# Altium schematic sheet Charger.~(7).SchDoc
size A3; SheetNumber: 2; SheetTotal: 2
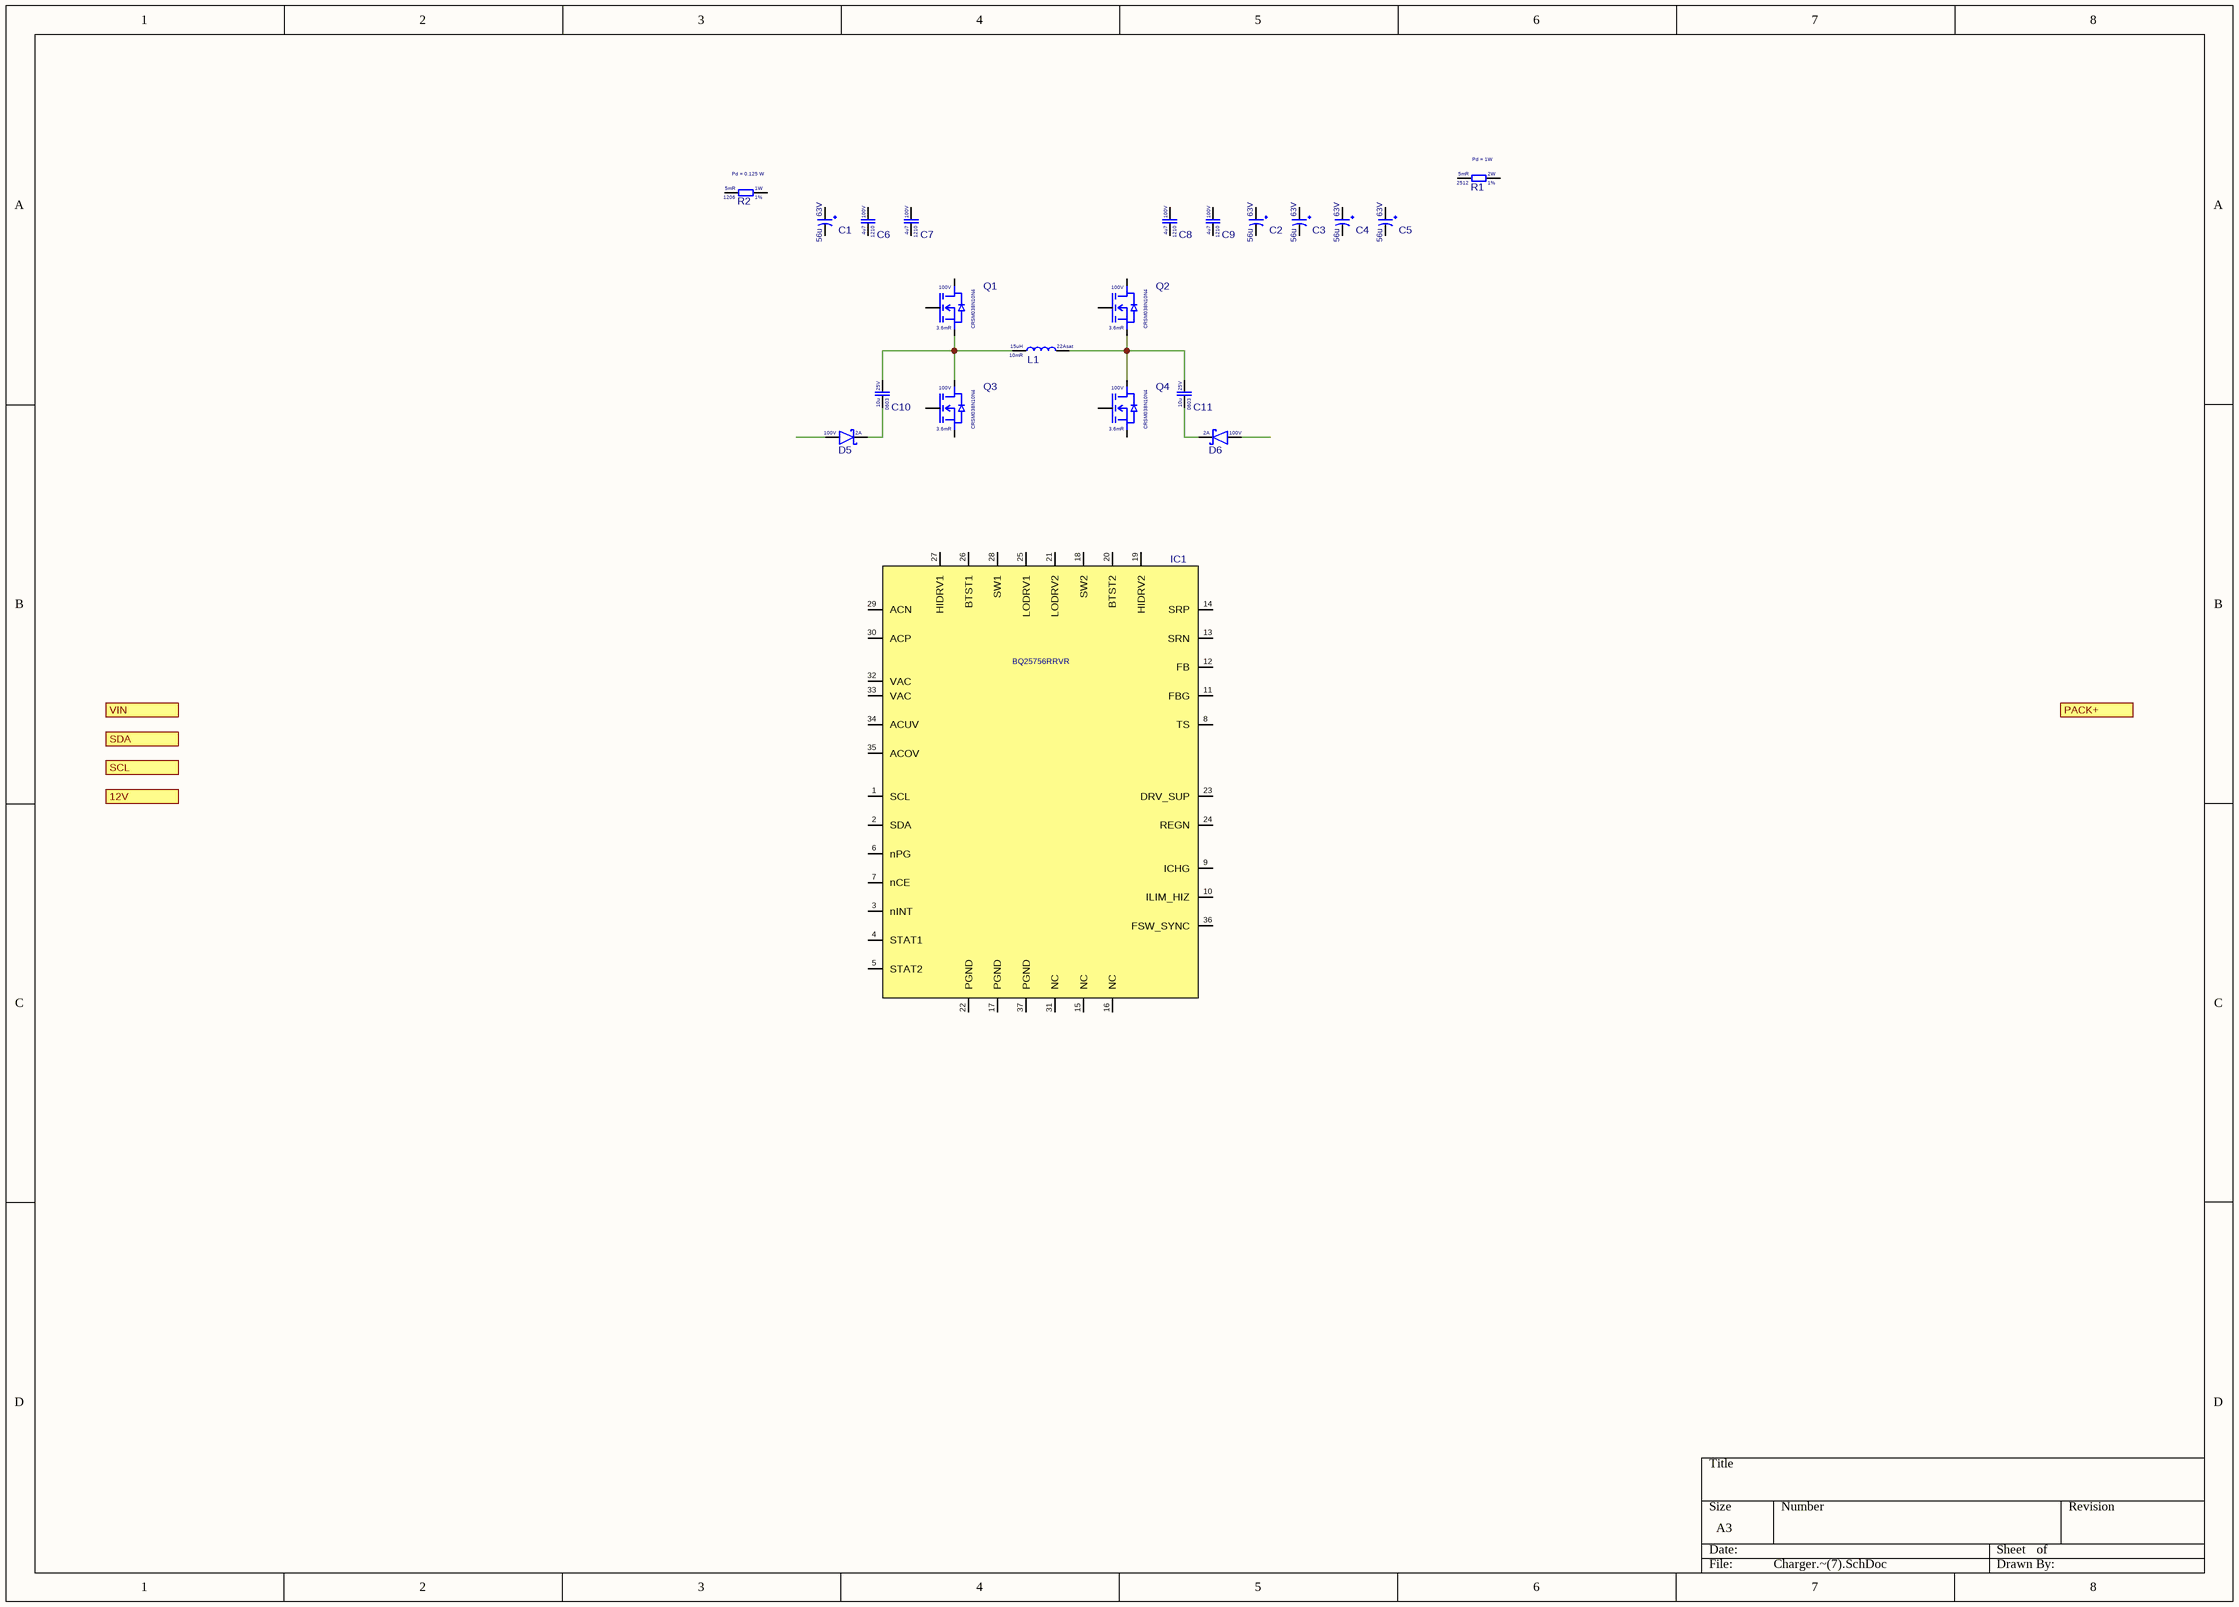
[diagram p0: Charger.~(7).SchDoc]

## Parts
C1  Voltage Rating: 63V  Capacitance: 56u  [CAP_SMD_10X10.2]  (hidden comment: EEHZA1J560P)
C2  Voltage Rating: 63V  Capacitance: 56u  [CAP_SMD_10X10.2]  (hidden comment: EEHZA1J560P)
C3  Voltage Rating: 63V  Capacitance: 56u  [CAP_SMD_10X10.2]  (hidden comment: EEHZA1J560P)
C4  Voltage Rating: 63V  Capacitance: 56u  [CAP_SMD_10X10.2]  (hidden comment: EEHZA1J560P)
C5  Voltage Rating: 63V  Capacitance: 56u  [CAP_SMD_10X10.2]  (hidden comment: EEHZA1J560P)
C6  Voltage Rating: 100V  Case Code (Imperial): 1210  Capacitance: 4u7  [CAP_1210]  (hidden comment: HMK325C7475KN-TE)
C7  Voltage Rating: 100V  Case Code (Imperial): 1210  Capacitance: 4u7  [CAP_1210]  (hidden comment: HMK325C7475KN-TE)
C8  Voltage Rating: 100V  Case Code (Imperial): 1210  Capacitance: 4u7  [CAP_1210]  (hidden comment: HMK325C7475KN-TE)
C9  Voltage Rating: 100V  Case Code (Imperial): 1210  Capacitance: 4u7  [CAP_1210]  (hidden comment: HMK325C7475KN-TE)
C10  Voltage Rating: 25V  Case Code (Imperial): 0603  Capacitance: 10u  [CAP 0603]  (hidden comment: CL10A106MA8NRNC)
C11  Voltage Rating: 25V  Case Code (Imperial): 0603  Capacitance: 10u  [CAP 0603]  (hidden comment: CL10A106MA8NRNC)
D5  Forward Current: 2A  Reverse Voltage: 100V  [SMAF]  (hidden comment: SS210F)
D6  Forward Current: 2A  Reverse Voltage: 100V  [SMAF]  (hidden comment: SS210F)
IC1  BQ25756RRVR  [VQFN-36(5x6)]
L1  Resistance: 10mR  Saturation current: 22Asat  Inductance: 15uH  [MTF1810-150M]  (hidden comment: MTF1810-150M)
Q1  Rds: 3.6mR  Voltage: 100V  [DFN-8 (5x6)]  (hidden comment: CRSM038N10N4)
Q2  Rds: 3.6mR  Voltage: 100V  [DFN-8 (5x6)]  (hidden comment: CRSM038N10N4)
Q3  Rds: 3.6mR  Voltage: 100V  [DFN-8 (5x6)]  (hidden comment: CRSM038N10N4)
Q4  Rds: 3.6mR  Voltage: 100V  [DFN-8 (5x6)]  (hidden comment: CRSM038N10N4)
R1  Pd = 1W  Resistance Tolerance: 1%  Resistance: 5mR  Power Rating: 2W  Case Code (Imperial): 2512  [RES_2512]
R2  Pd = 0.125 W  Resistance Tolerance: 1%  Resistance: 5mR  Power Rating: 1W  Case Code (Imperial): 1206  [RES_1206]

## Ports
12V (see Arhitecture[5B]), PACK+ (see Arhitecture[6B]), SCL (see Arhitecture[5B]), SDA (see Arhitecture[5B]), VIN (see Arhitecture[5B])

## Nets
NetC10_1: C10.1 D5.K
NetC10_2: C10.2 L1.1 Q1.S Q3.D
NetC11_1: C11.1 D6.K
NetC11_2: C11.2 L1.2 Q2.S Q4.D

Not connected (* = marked no-connect by the designer): C1 + -; C2 + -; C3 + -; C4 + -; C5 + -; C6 1 2; C7 1 2; C8 1 2; C9 1 2; D5 A; D6 A; IC1 1(SCL) 2(SDA) 3(nINT) 4(STAT1) 5(STAT2) 6(nPG) 7(nCE) 8(TS) 9(ICHG) 10(ILIM_HIZ) 11(FBG) 12(FB) 13(SRN) 14(SRP) 15(NC) 16(NC) 17(PGND) 18(SW2) 19(HIDRV2) 20(BTST2) 21(LODRV2) 22(PGND) 23(DRV_SUP) 24(REGN) 25(LODRV1) 26(BTST1) 27(HIDRV1) 28(SW1) 29(ACN) 30(ACP) 31(NC) 32(VAC) 33(VAC) 34(ACUV) 35(ACOV) 36(FSW_SYNC) 37(PGND); Q1 D G; Q2 D G; Q3 G S; Q4 G S; R1 1 2; R2 1 2

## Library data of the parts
C1-C5 = EEHZA1J560P: Cap AL-EL 56uF 63V 30mR 1.8Ar SMD 10x10.2mm; Manufacturer: Panasonic
C6-C9 = HMK325C7475KN-TE: Cap 4.7uF 100V 1210 X7R; Manufacturer: Taiyo Yuden
C10 C11 = CL10A106MA8NRNC: Cap 10uF 25V 0603 X5R; Manufacturer: Samsung
D5 D6 = SS210F: Schottky 100V 2A 850mVf SMAF; Manufacturer: GOODWORK
IC1 = BQ25756RRVR: Charger IC; Manufacturer: Texas Instruments
L1 = MTF1810-150M: Inductor 15uH 22Asat 10mR SMD 18x18x9 mm; Manufacturer: COILMX
Q1-Q4 = CRSM038N10N4: Nmos 100V 100A 3.6mR DFN-8(5x6); Manufacturer: CRMICRO
R1 = RLM25FEER005: Res 5mR 2512 1% 2W; Manufacturer: TA-I Tech
R2 = FRM121WFR005TM: Res 5mR 1206 1% 1W; Manufacturer: FOJAN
